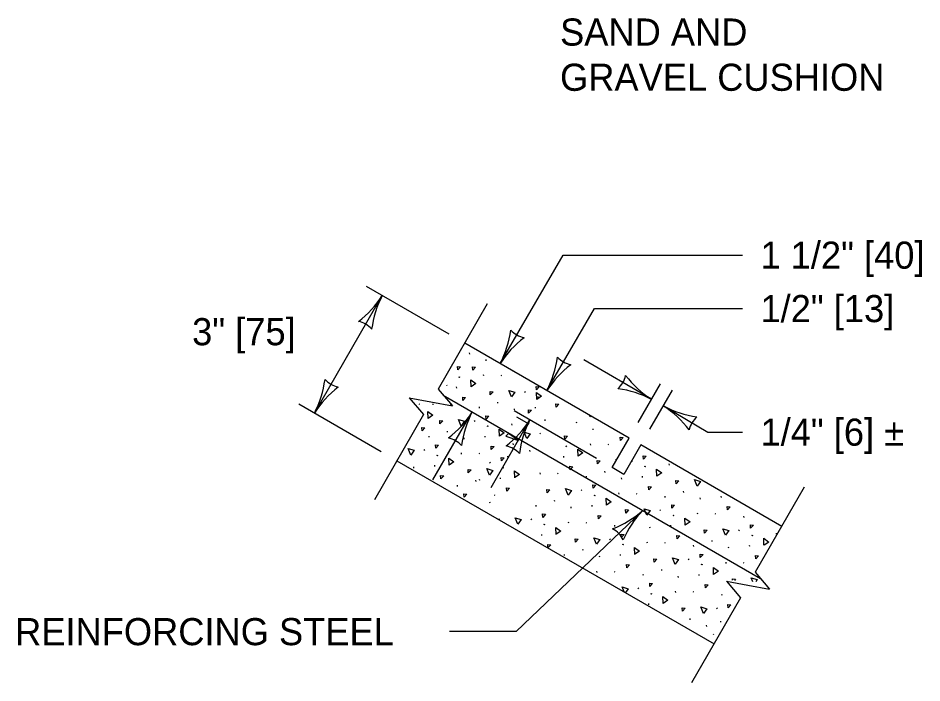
# Model space of a CAD drawing. Extents: x 49991.4 to 50021, y 49987.6 to 50011.4.
# Drawn here: x 50008.456 to 50010.456, y 49990.163 to 49991.633 of the extents above; entities that cross this region are included whole.
import ezdxf

# ---------------------------------------------------------------- set-up
doc = ezdxf.new("R2010")
doc.units = 0
for name, color, linetype in [('Level 1', 7, 'Continuous'), ('Level 2', 7, 'Continuous'), ('Level 3', 7, 'Continuous'), ('Level 6', 7, 'Continuous')]:
    doc.layers.add(name, color=color, linetype=linetype)

msp = doc.modelspace()

# ---------------------------------------------------------------- linework, layer by layer
at = {"layer": 'Level 1'}
for p, q in [((50009.8081, 49990.7041), (50009.4443, 49990.9143)), ((50009.4444, 49990.9143), (50009.4444, 49990.9143)), ((50009.4554, 49990.89), (50009.4549, 49990.8926)), ((50009.492, 49990.8753), (50009.4918, 49990.8779)), ((50009.4306, 49990.8397), (50009.4322, 49990.839)), ((50009.4318, 49990.8397), (50009.4336, 49990.839)), ((50009.4863, 49990.8417), (50009.4859, 49990.8444)), ((50009.5239, 49990.8437), (50009.5256, 49990.8428)), ((50009.4053, 49990.8197), (50009.405, 49990.8213)), ((50009.397, 49990.7989), (50010.099, 49990.3934)), ((50009.4269, 49990.8147), (50009.4265, 49990.8173)), ((50009.5767, 49990.8075), (50009.5781, 49990.8054)), ((50009.343, 49990.78), (50009.3442, 49990.7793)), ((50009.3748, 49990.7775), (50009.3745, 49990.78)), ((50009.4124, 49990.7792), (50009.4142, 49990.7785)), ((50009.5179, 49990.7813), (50009.5177, 49990.784)), ((50009.6047, 49990.7955), (50009.6065, 49990.7945)), ((50009.606, 49990.7955), (50009.6078, 49990.7946)), ((50009.4772, 49990.7704), (50009.4768, 49990.7731)), ((50009.5548, 49990.7666), (50009.5546, 49990.7692)), ((50009.601, 49990.7703), (50009.6008, 49990.7729)), ((50009.4652, 49990.743), (50009.4667, 49990.7412)), ((50009.5866, 49990.735), (50009.5597, 49990.7507)), ((50009.6227, 49990.7427), (50009.6223, 49990.7452)), ((50009.6922, 49990.737), (50009.6918, 49990.7396)), ((50009.4065, 49990.717), (50009.4063, 49990.7196)), ((50009.4933, 49990.7311), (50009.4951, 49990.7303)), ((50009.4946, 49990.7311), (50009.4963, 49990.7303)), ((50009.549, 49990.733), (50009.5487, 49990.7357)), ((50009.7289, 49990.7223), (50009.7286, 49990.7248)), ((50009.3658, 49990.7061), (50009.3654, 49990.7087)), ((50009.4434, 49990.7022), (50009.443, 49990.7049)), ((50009.4896, 49990.706), (50009.4893, 49990.7086)), ((50009.6108, 49990.7153), (50009.6122, 49990.7133)), ((50009.7707, 49990.6394), (50009.8081, 49990.7041)), ((50009.5521, 49990.6892), (50009.5518, 49990.6919)), ((50009.6675, 49990.6867), (50009.6692, 49990.6858)), ((50009.6688, 49990.6868), (50009.6704, 49990.6858)), ((50009.7232, 49990.6888), (50009.7229, 49990.6915)), ((50009.7608, 49990.6907), (50009.7625, 49990.6897)), ((50009.8342, 49990.689), (50009.7967, 49990.624)), ((50010.1457, 49990.509), (50009.8342, 49990.689)), ((50009.3538, 49990.6787), (50009.3552, 49990.6768)), ((50009.3819, 49990.6667), (50009.3836, 49990.6659)), ((50009.3832, 49990.6667), (50009.3848, 49990.6659)), ((50009.4375, 49990.6688), (50009.4373, 49990.6713)), ((50009.4752, 49990.6706), (50009.4769, 49990.6698)), ((50009.5398, 49990.6618), (50009.5396, 49990.6644)), ((50009.5889, 49990.6745), (50009.5885, 49990.6772)), ((50009.6638, 49990.6615), (50009.6635, 49990.6642)), ((50009.2943, 49990.6541), (50009.996, 49990.2493)), ((50009.295, 49990.6537), (50009.2949, 49990.6551)), ((50009.3319, 49990.6378), (50009.3316, 49990.6405)), ((50009.3781, 49990.6415), (50009.3779, 49990.6443)), ((50009.4994, 49990.6511), (50009.5008, 49990.6491)), ((50009.5274, 49990.6391), (50009.5291, 49990.6382)), ((50009.5286, 49990.6391), (50009.5304, 49990.6382)), ((50009.7967, 49990.624), (50009.7707, 49990.6394)), ((50009.814, 49990.654), (50009.815, 49990.6525)), ((50009.8417, 49990.6424), (50009.8434, 49990.6415)), ((50009.843, 49990.6424), (50009.8446, 49990.6415)), ((50009.8973, 49990.6444), (50009.8971, 49990.647)), ((50009.6118, 49990.6244), (50009.6113, 49990.627)), ((50009.6494, 49990.6263), (50009.651, 49990.6255)), ((50009.7141, 49990.6175), (50009.7137, 49990.6201)), ((50009.7549, 49990.6283), (50009.7547, 49990.631)), ((50009.8379, 49990.6172), (50009.8377, 49990.62)), ((50009.4284, 49990.5974), (50009.4282, 49990.6)), ((50009.4693, 49990.6083), (50009.4691, 49990.6109)), ((50009.4775, 49990.6102), (50009.477, 49990.6128)), ((50009.5237, 49990.6139), (50009.5232, 49990.6164)), ((50009.7917, 49990.6135), (50009.7914, 49990.6162)), ((50009.7022, 49990.59), (50009.7036, 49990.5881)), ((50009.7859, 49990.5801), (50009.7856, 49990.5828)), ((50009.8235, 49990.5819), (50009.8253, 49990.581)), ((50009.9291, 49990.584), (50009.9288, 49990.5866)), ((50009.5003, 49990.56), (50009.4999, 49990.5626)), ((50009.5093, 49990.5786), (50009.5109, 49990.5777)), ((50009.6434, 49990.564), (50009.6432, 49990.5665)), ((50009.7302, 49990.578), (50009.732, 49990.5772)), ((50009.7316, 49990.578), (50009.7332, 49990.5772)), ((50009.8882, 49990.5731), (50009.888, 49990.5757)), ((50009.9658, 49990.5692), (50009.9655, 49990.5719)), ((50010.0122, 49990.573), (50010.0117, 49990.5755)), ((50009.6026, 49990.5531), (50009.6023, 49990.5558)), ((50009.6802, 49990.5492), (50009.68, 49990.5518)), ((50009.7265, 49990.5529), (50009.7262, 49990.5555)), ((50009.8764, 49990.5457), (50009.8779, 49990.5438)), ((50009.5906, 49990.5258), (50009.5922, 49990.5237)), ((50009.8177, 49990.5196), (50009.8175, 49990.5223)), ((50009.9045, 49990.5337), (50009.9061, 49990.533)), ((50009.9057, 49990.5337), (50009.9073, 49990.533)), ((50009.9601, 49990.5357), (50009.9597, 49990.5383)), ((50009.9978, 49990.5377), (50009.9994, 49990.5368)), ((50010.0624, 49990.5288), (50010.0621, 49990.5315)), ((50009.6188, 49990.5138), (50009.6206, 49990.5129)), ((50009.6201, 49990.5138), (50009.6218, 49990.5129)), ((50009.6745, 49990.5157), (50009.6741, 49990.5184)), ((50009.7121, 49990.5177), (50009.7138, 49990.5168)), ((50009.7768, 49990.5088), (50009.7766, 49990.5114)), ((50009.8544, 49990.5049), (50009.8541, 49990.5075)), ((50009.9007, 49990.5086), (50009.9003, 49990.5113)), ((50010.0504, 49990.5015), (50010.052, 49990.4994)), ((50009.6151, 49990.4886), (50009.6147, 49990.4912)), ((50009.7649, 49990.4814), (50009.7664, 49990.4794)), ((50010.0786, 49990.4895), (50010.0804, 49990.4886)), ((50010.0799, 49990.4895), (50010.0816, 49990.4886)), ((50010.1343, 49990.4914), (50010.1339, 49990.4941)), ((50009.793, 49990.4694), (50009.7947, 49990.4686)), ((50009.7943, 49990.4694), (50009.796, 49990.4686)), ((50009.8487, 49990.4715), (50009.8483, 49990.474)), ((50009.8863, 49990.4732), (50009.888, 49990.4724)), ((50009.951, 49990.4644), (50009.9507, 49990.4671)), ((50009.9918, 49990.4753), (50009.9916, 49990.478)), ((50010.0286, 49990.4606), (50010.0283, 49990.4632)), ((50010.0749, 49990.4643), (50010.0745, 49990.4668)), ((50009.6653, 49990.4445), (50009.6651, 49990.447)), ((50009.7063, 49990.4554), (50009.706, 49990.4579)), ((50009.743, 49990.4406), (50009.7427, 49990.4431)), ((50009.7893, 49990.4442), (50009.7889, 49990.4469)), ((50009.939, 49990.4371), (50009.9404, 49990.4352)), ((50009.9671, 49990.4252), (50009.9689, 49990.4243)), ((50009.9685, 49990.4252), (50009.9702, 49990.4243)), ((50010.0227, 49990.427), (50010.0225, 49990.4297)), ((50010.0605, 49990.429), (50010.0622, 49990.4281)), ((50009.7372, 49990.4071), (50009.7368, 49990.4098)), ((50009.7749, 49990.409), (50009.7766, 49990.4082)), ((50009.8396, 49990.4001), (50009.8392, 49990.4027)), ((50009.8804, 49990.411), (50009.8802, 49990.4136)), ((50009.9171, 49990.3962), (50009.9169, 49990.3989)), ((50009.9633, 49990.4), (50009.9631, 49990.4026)), ((50009.8276, 49990.3727), (50009.829, 49990.3708)), ((50009.8556, 49990.3607), (50009.8575, 49990.3599)), ((50009.8571, 49990.3607), (50009.8587, 49990.3599)), ((50009.9113, 49990.3628), (50009.9111, 49990.3653)), ((50009.949, 49990.3646), (50009.9508, 49990.3638)), ((50010.0137, 49990.3557), (50010.0135, 49990.3584)), ((50009.8519, 49990.3356), (50009.8517, 49990.3382)), ((50010.0018, 49990.3285), (50010.0033, 49990.3265)), ((50009.9432, 49990.3023), (50009.9429, 49990.3049)), ((50010.0111, 49990.2967), (50010.0109, 49990.2992)), ((50009.9799, 49990.2875), (50009.9796, 49990.2902)), ((50009.9938, 49990.2714), (50009.9952, 49990.2694))]:
    msp.add_line(p, q, dxfattribs=at)
for points in [[(50009.429, 49990.8549), (50009.4284, 49990.8624), (50009.4351, 49990.8615), (50009.429, 49990.8549)], [(50009.4622, 49990.8545), (50009.4616, 49990.862), (50009.4682, 49990.8611), (50009.4622, 49990.8545)], [(50009.5518, 49990.8517), (50009.5518, 49990.8523)], [(50009.5522, 49990.8521), (50009.5518, 49990.8517)], [(50009.4584, 49990.8174), (50009.4579, 49990.8329), (50009.4691, 49990.8248), (50009.4586, 49990.8175)], [(50009.501, 49990.8002), (50009.5004, 49990.8076), (50009.507, 49990.8068), (50009.501, 49990.8002)], [(50009.5478, 49990.7953), (50009.5418, 49990.8096), (50009.5551, 49990.8058), (50009.5479, 49990.7955)], [(50009.6032, 49990.8106), (50009.6025, 49990.818), (50009.6092, 49990.8173), (50009.6032, 49990.8106)], [(50009.6039, 49990.7896), (50009.6034, 49990.8051), (50009.6145, 49990.7969), (50009.6041, 49990.7897)], [(50009.4404, 49990.7874), (50009.4398, 49990.7948), (50009.4464, 49990.794), (50009.4404, 49990.7874)], [(50009.6464, 49990.7724), (50009.6459, 49990.7799), (50009.6525, 49990.779), (50009.6464, 49990.7724)], [(50009.3633, 49990.7477), (50009.3627, 49990.7631), (50009.374, 49990.755), (50009.3635, 49990.7478)], [(50009.5858, 49990.7596), (50009.5854, 49990.767), (50009.592, 49990.7662), (50009.5858, 49990.7596)], [(50009.3896, 49990.7358), (50009.389, 49990.7432), (50009.3956, 49990.7425), (50009.3896, 49990.7358)], [(50009.4363, 49990.7308), (50009.4305, 49990.7452), (50009.4437, 49990.7415), (50009.4364, 49990.7311)], [(50009.4918, 49990.7462), (50009.4911, 49990.7537), (50009.4978, 49990.7528), (50009.4918, 49990.7462)], [(50009.7219, 49990.751), (50009.7202, 49990.7549)], [(50009.7234, 49990.7531), (50009.7221, 49990.7511)], [(50009.3499, 49990.7201), (50009.3494, 49990.7276), (50009.356, 49990.7269), (50009.3499, 49990.7201)], [(50009.5212, 49990.7087), (50009.5207, 49990.7242), (50009.5318, 49990.716), (50009.5214, 49990.7088)], [(50009.535, 49990.7082), (50009.5632, 49990.6989), (50009.5411, 49990.7147), (50009.535, 49990.7082)], [(50009.5817, 49990.7032), (50009.5759, 49990.7176), (50009.5892, 49990.7137), (50009.582, 49990.7034)], [(50009.6659, 49990.7019), (50009.6653, 49990.7093), (50009.672, 49990.7086), (50009.6659, 49990.7019)], [(50009.7888, 49990.6987), (50009.7882, 49990.7062), (50009.7948, 49990.7053), (50009.7888, 49990.6987)], [(50009.3249, 49990.6666), (50009.3191, 49990.6809), (50009.3323, 49990.6772), (50009.325, 49990.6667)], [(50009.3803, 49990.682), (50009.3797, 49990.6894), (50009.3863, 49990.6885), (50009.3803, 49990.682)], [(50009.5031, 49990.6787), (50009.5026, 49990.6861), (50009.5092, 49990.6854), (50009.5031, 49990.6787)], [(50009.6954, 49990.6643), (50009.6947, 49990.6798), (50009.706, 49990.6717), (50009.6956, 49990.6644)], [(50009.4098, 49990.6444), (50009.4092, 49990.6599), (50009.4204, 49990.6518), (50009.4099, 49990.6445)], [(50009.5257, 49990.6542), (50009.5252, 49990.6616), (50009.5318, 49990.6609), (50009.5257, 49990.6542)], [(50009.8401, 49990.6577), (50009.8395, 49990.6651), (50009.8461, 49990.6642), (50009.8401, 49990.6577)], [(50009.6773, 49990.6343), (50009.6767, 49990.6418), (50009.6834, 49990.641), (50009.6773, 49990.6343)], [(50009.7379, 49990.6471), (50009.7374, 49990.6546), (50009.744, 49990.6538), (50009.7379, 49990.6471)], [(50009.7796, 49990.6546), (50009.7788, 49990.6566), (50009.7804, 49990.656)], [(50009.3917, 49990.6144), (50009.3911, 49990.6217), (50009.3978, 49990.6211), (50009.3917, 49990.6144)], [(50009.4523, 49990.6272), (50009.4516, 49990.6346), (50009.4583, 49990.6338), (50009.4523, 49990.6272)], [(50009.499, 49990.6222), (50009.4932, 49990.6366), (50009.5065, 49990.6328), (50009.4992, 49990.6225)], [(50009.5552, 49990.6165), (50009.5546, 49990.632), (50009.5659, 49990.6239), (50009.5555, 49990.6168)], [(50009.8695, 49990.6201), (50009.869, 49990.6356), (50009.8802, 49990.6274), (50009.8697, 49990.6202)], [(50009.7286, 49990.5933), (50009.728, 49990.6007), (50009.7346, 49990.5999), (50009.7286, 49990.5933)], [(50009.9121, 49990.6028), (50009.9114, 49990.6103), (50009.9181, 49990.6095), (50009.9121, 49990.6028)], [(50009.9588, 49990.5978), (50009.953, 49990.6123), (50009.9663, 49990.6085), (50009.959, 49990.5982)], [(50009.4429, 49990.5733), (50009.4425, 49990.5807), (50009.4491, 49990.5799), (50009.4429, 49990.5733)], [(50009.5372, 49990.5866), (50009.5365, 49990.5941), (50009.5433, 49990.5932), (50009.5372, 49990.5866)], [(50009.6265, 49990.5829), (50009.6258, 49990.5903), (50009.6326, 49990.5894), (50009.6265, 49990.5829)], [(50009.6733, 49990.5779), (50009.6674, 49990.5924), (50009.6806, 49990.5885), (50009.6734, 49990.5782)], [(50009.8515, 49990.59), (50009.8509, 49990.5974), (50009.8576, 49990.5966), (50009.8515, 49990.59)], [(50009.7582, 49990.5557), (50009.7575, 49990.5711), (50009.7686, 49990.5631), (50009.7583, 49990.5558)], [(50009.8006, 49990.5384), (50009.8, 49990.546), (50009.8067, 49990.5452), (50009.8006, 49990.5384)], [(50009.8474, 49990.5335), (50009.8416, 49990.5479), (50009.8549, 49990.5442), (50009.8476, 49990.5337)], [(50009.9027, 49990.549), (50009.9023, 49990.5564), (50009.9089, 49990.5555), (50009.9027, 49990.549)], [(50010.0257, 49990.5457), (50010.025, 49990.5531), (50010.0318, 49990.5523), (50010.0257, 49990.5457)], [(50009.517, 49990.5257), (50009.5211, 49990.5251), (50009.5199, 49990.5239)], [(50009.5618, 49990.5136), (50009.556, 49990.528), (50009.5692, 49990.524), (50009.5619, 49990.5138)], [(50009.6172, 49990.5289), (50009.6166, 49990.5365), (50009.6232, 49990.5356), (50009.6172, 49990.5289)], [(50009.74, 49990.5257), (50009.7395, 49990.5332), (50009.7462, 49990.5323), (50009.74, 49990.5257)], [(50009.9323, 49990.5114), (50009.9316, 49990.5269), (50009.9429, 49990.5188), (50009.9325, 49990.5115)], [(50009.6468, 49990.4913), (50009.6461, 49990.5068), (50009.6572, 49990.4986), (50009.6469, 49990.4914)], [(50009.9749, 49990.4942), (50009.9742, 49990.5016), (50009.9809, 49990.5008), (50009.9749, 49990.4942)], [(50010.0216, 49990.4893), (50010.0157, 49990.5036), (50010.029, 49990.4997), (50010.0217, 49990.4895)], [(50010.077, 49990.5046), (50010.0764, 49990.5122), (50010.083, 49990.5113), (50010.077, 49990.5046)], [(50009.6892, 49990.4742), (50009.6886, 49990.4816), (50009.6953, 49990.4808), (50009.6892, 49990.4742)], [(50009.7358, 49990.4693), (50009.7301, 49990.4836), (50009.7434, 49990.4798), (50009.7362, 49990.4694)], [(50009.7913, 49990.4847), (50009.7908, 49990.492), (50009.7974, 49990.4913), (50009.7913, 49990.4847)], [(50009.9143, 49990.4814), (50009.9136, 49990.4887), (50009.9203, 49990.4881), (50009.9143, 49990.4814)], [(50010.1064, 49990.467), (50010.1059, 49990.4825), (50010.117, 49990.4743), (50010.1067, 49990.4671)], [(50009.6286, 49990.4614), (50009.628, 49990.4688), (50009.6348, 49990.4679), (50009.6286, 49990.4614)], [(50009.8209, 49990.447), (50009.8202, 49990.4624), (50009.8314, 49990.4544), (50009.8211, 49990.4472)], [(50009.9101, 49990.4248), (50009.9044, 49990.4392), (50009.9176, 49990.4355), (50009.9103, 49990.4252)], [(50009.9655, 49990.4402), (50009.965, 49990.4477), (50009.9716, 49990.4469), (50009.9655, 49990.4402)], [(50010.0884, 49990.4371), (50010.0878, 49990.4445), (50010.0946, 49990.4436), (50010.0884, 49990.4371)], [(50009.8028, 49990.417), (50009.8022, 49990.4245), (50009.8089, 49990.4236), (50009.8028, 49990.417)], [(50009.8634, 49990.4299), (50009.8628, 49990.4374), (50009.8695, 49990.4365), (50009.8634, 49990.4299)], [(50009.9951, 49990.4027), (50009.9945, 49990.4182), (50010.0056, 49990.4101), (50009.9952, 49990.4028)], [(50009.8541, 49990.376), (50009.8536, 49990.3834), (50009.8602, 49990.3825), (50009.8541, 49990.376)], [(50009.977, 49990.3727), (50009.9764, 49990.38), (50009.9831, 49990.3794), (50009.977, 49990.3727)], [(50010.0371, 49990.3897), (50010.0369, 49990.3929), (50010.0436, 49990.392), (50010.0412, 49990.3894)], [(50010.0818, 49990.3866), (50010.0784, 49990.395), (50010.0918, 49990.3912), (50010.0884, 49990.3863)], [(50009.7973, 49990.3639), (50009.7928, 49990.3749), (50009.806, 49990.3711), (50009.7999, 49990.3623)], [(50009.8837, 49990.3384), (50009.883, 49990.3539), (50009.8941, 49990.3457), (50009.8838, 49990.3385)], [(50009.9262, 49990.3212), (50009.9255, 49990.3286), (50009.9322, 49990.3278), (50009.9262, 49990.3212)], [(50009.9728, 49990.3162), (50009.967, 49990.3307), (50009.9803, 49990.3268), (50009.973, 49990.3165)], [(50010.0271, 49990.3288), (50010.0266, 49990.3362), (50010.0332, 49990.3354), (50010.0271, 49990.3288)]]:
    msp.add_lwpolyline(points, dxfattribs=at)
at = {"layer": 'Level 3'}
for p, q in [((50009.5229, 49990.8689), (50009.662, 49991.1089)), ((50009.662, 49991.1089), (50010.0587, 49991.1089)), ((50009.4097, 49990.9344), (50009.2273, 49991.0397)), ((50009.1117, 49990.7595), (50009.2619, 49991.0197)), ((50009.6262, 49990.8092), (50009.7314, 49990.9907)), ((50009.7314, 49990.9907), (50010.0587, 49990.9907)), ((50009.8578, 49990.79), (50009.7077, 49990.877)), ((50009.8281, 49990.7387), (50009.8778, 49990.8246)), ((50009.8542, 49990.7237), (50009.9041, 49990.81)), ((50009.2597, 49990.6741), (50009.0771, 49990.7795)), ((50009.374, 49990.6119), (50009.461, 49990.762)), ((50009.7361, 49990.6594), (50009.5541, 49990.7643)), ((50009.8841, 49990.7754), (50009.982, 49990.7174)), ((50009.5887, 49990.7443), (50009.5021, 49990.5941)), ((50009.982, 49990.7174), (50010.0587, 49990.7174)), ((50009.8382, 49990.5441), (50009.5584, 49990.2761)), ((50009.5584, 49990.2761), (50009.4105, 49990.2761))]:
    msp.add_line(p, q, dxfattribs=at)
for centre, radius, start, end in [((50009.0741, 49991.1387), 0.2223, 307.4604, 327.6439), ((50009.4692, 49990.9133), 0.233, 152.8317, 172.0815), ((50009.1978, 49990.9087), 0.0548, 42.1432, 77.8656), ((50009.3158, 49990.9756), 0.233, 332.7386, 351.9885), ((50009.5872, 49990.9799), 0.0548, 222.0501, 257.7725), ((50009.7105, 49990.7496), 0.2223, 127.3673, 147.5508), ((50009.4191, 49990.916), 0.233, 332.7166, 351.9664), ((50009.6905, 49990.9201), 0.0548, 222.0281, 257.7505), ((50009.8138, 49990.6899), 0.2223, 127.3453, 147.5288), ((50009.7468, 49990.8542), 0.0548, 312.0558, 347.7782), ((50009.977, 49990.9776), 0.2223, 217.373, 237.5565), ((50008.9044, 49990.8659), 0.233, 332.8317, 352.0815), ((50009.1758, 49990.8706), 0.0548, 222.1432, 257.8656), ((50009.2995, 49990.6405), 0.2223, 127.4604, 147.6439), ((50009.7511, 49990.5828), 0.233, 62.7443, 81.9941), ((50009.2734, 49990.8813), 0.2223, 307.3526, 327.5361), ((50009.6681, 49990.6552), 0.233, 152.7239, 171.9737), ((50009.7631, 49990.5889), 0.2223, 36.8473, 57.0308), ((50009.9927, 49990.9815), 0.233, 242.2186, 261.4685), ((50009.4009, 49990.8633), 0.2223, 307.4716, 327.6551), ((50009.796, 49990.638), 0.233, 152.8429, 172.0927), ((50009.9944, 49990.7101), 0.0548, 131.5301, 167.2525), ((50009.3967, 49990.6511), 0.0548, 42.0354, 77.7577), ((50009.5247, 49990.6333), 0.0548, 42.1544, 77.8767), ((50009.6912, 49990.7109), 0.2223, 291.222, 311.4055), ((50010.0075, 49990.384), 0.233, 136.5933, 155.8432), ((50009.7456, 49990.4554), 0.0548, 25.9048, 61.6272)]:
    msp.add_arc(centre, radius, start, end, dxfattribs=at)
at = {"layer": 'Level 6'}
for p, q in [((50009.4943, 49991.0009), (50009.3855, 49990.8124)), ((50009.3856, 49990.8123), (50009.4171, 49990.7754)), ((50009.3217, 49990.793), (50009.3694, 49990.7842)), ((50009.3217, 49990.793), (50009.3532, 49990.7561)), ((50009.3694, 49990.7842), (50009.4171, 49990.7754)), ((50009.3532, 49990.7561), (50009.2444, 49990.5675)), ((50010.1957, 49990.5956), (50010.0871, 49990.4074)), ((50010.0872, 49990.4073), (50010.1187, 49990.3704)), ((50010.0233, 49990.388), (50010.071, 49990.3792)), ((50010.0233, 49990.388), (50010.0548, 49990.3511)), ((50010.071, 49990.3792), (50010.1187, 49990.3704)), ((50010.0548, 49990.3511), (50009.9461, 49990.1627))]:
    msp.add_line(p, q, dxfattribs=at)

# ---------------------------------------------------------------- texts
at = {"layer": 'Level 2'}
for s, p in [('SAND AND', (50009.6553, 49991.5724)), ('GRAVEL CUSHION', (50009.6553, 49991.4724)), ('1 1/2" [40]', (50010.0987, 49991.0789)), ('1/2" [13]', (50010.0987, 49990.9607)), ('3" [75]', (50008.8411, 49990.9096)), ('1/4" [6] ±', (50010.0987, 49990.6874)), ('REINFORCING STEEL', (50008.4494, 49990.2461))]:
    msp.add_text(s, height=0.06, dxfattribs=at).set_placement(p)

doc.saveas('drawing.dxf')
